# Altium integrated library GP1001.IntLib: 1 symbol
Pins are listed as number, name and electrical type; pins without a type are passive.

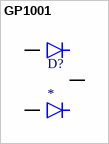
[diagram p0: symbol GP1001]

## GP1001
designator D?
10A, 50V, Standard Recovery Rectifier; MP: GP1001; MF: Taiwan Semiconductor
footprint TO254P1050X476X2020-3
pins: 1 A1, 2 C, 3 A2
